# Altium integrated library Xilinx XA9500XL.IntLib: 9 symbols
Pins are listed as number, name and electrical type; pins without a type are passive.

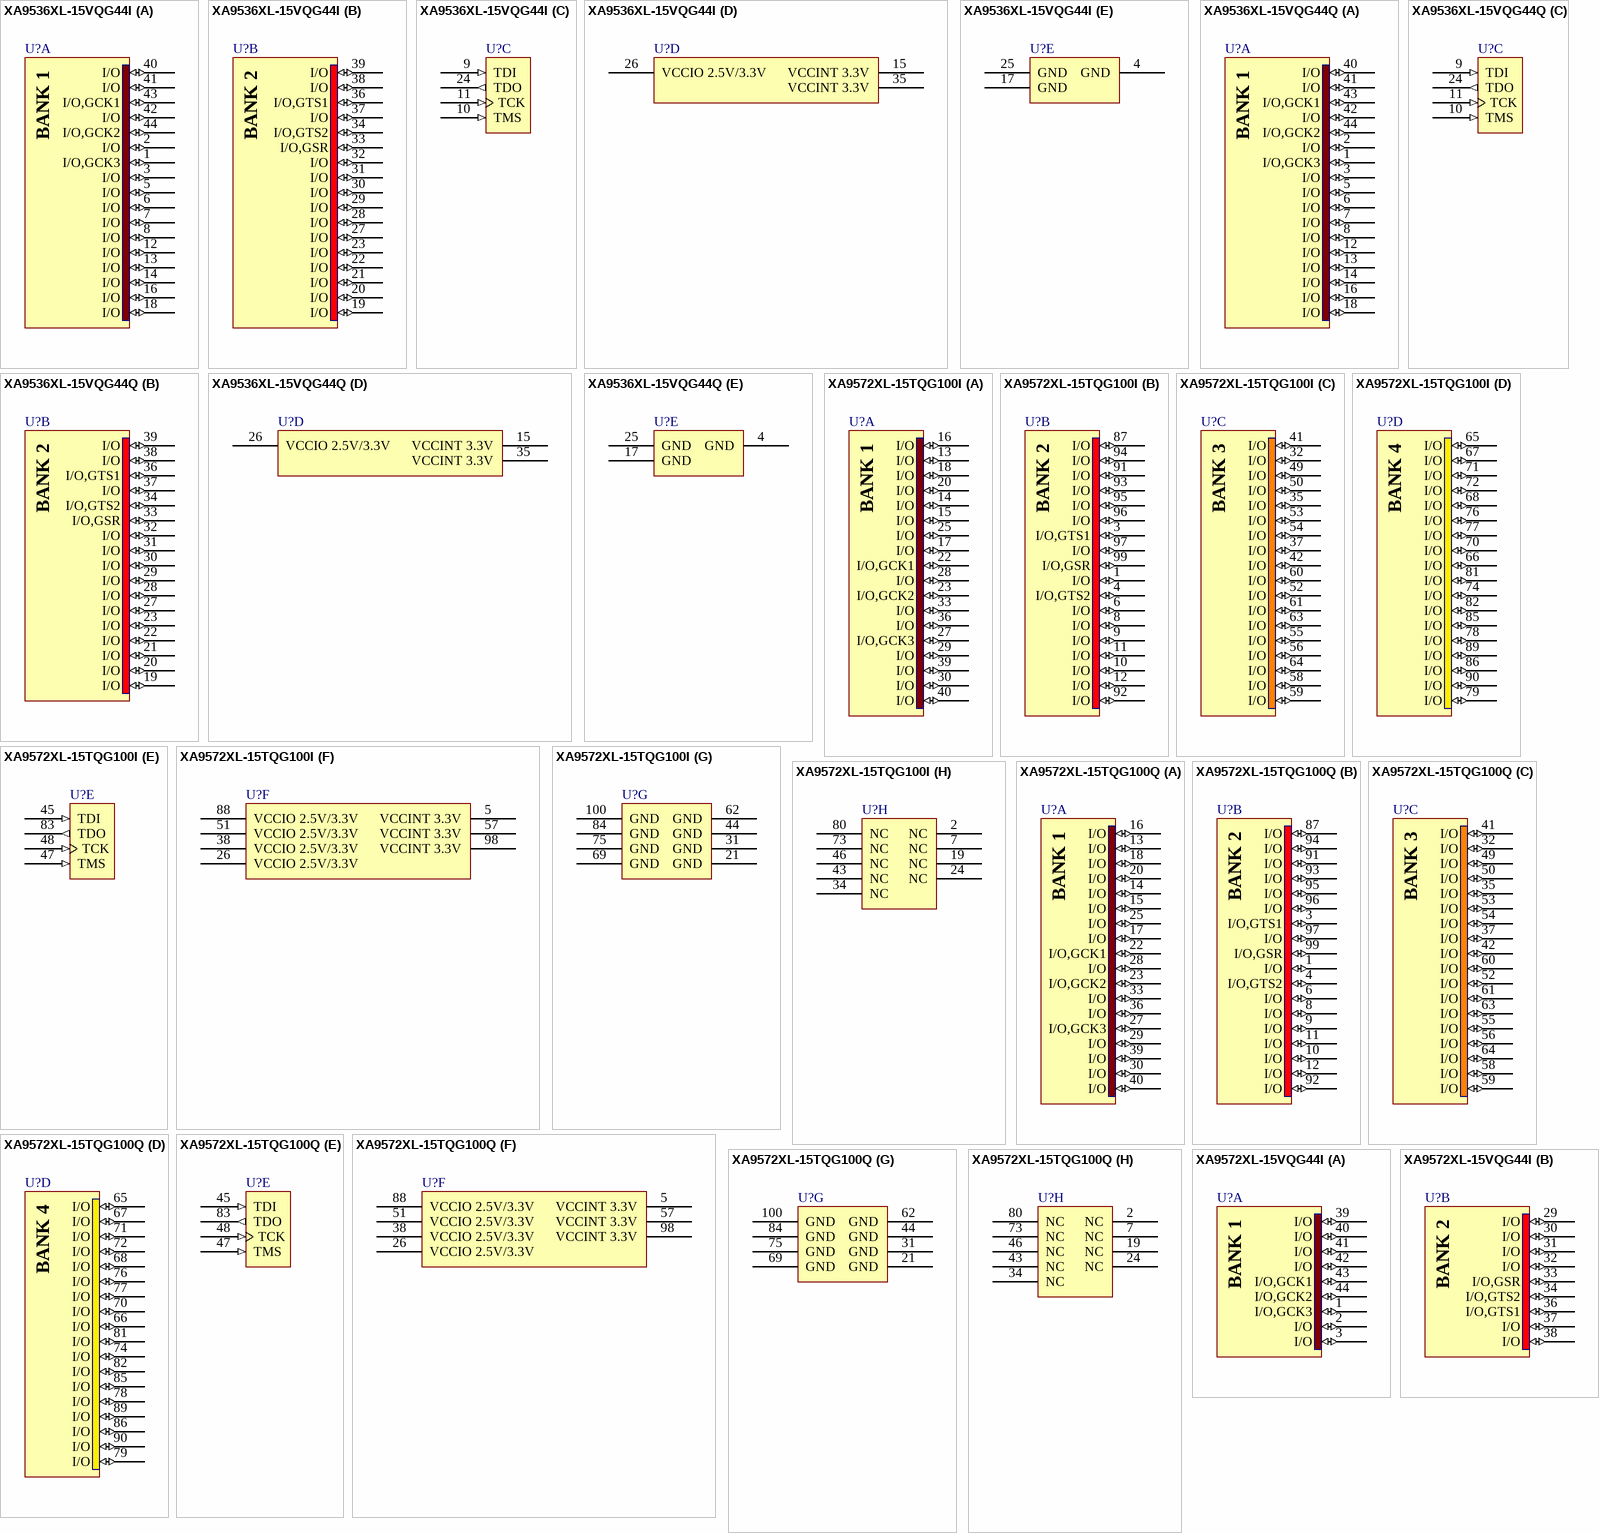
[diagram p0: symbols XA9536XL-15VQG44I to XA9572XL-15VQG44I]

## XA9536XL-15VQG44I
designator U?
XA9500XL Automotive, 36 Macrocell CPLD, 36 User I/Os, 44-Pin VQFP, Speed 15, Industrial Grade, Pb-Free
footprint VQG44_N (Thin QFP, 44-Leads, Body 10x10mm, Pitch 0.8mm, IPC Medium Density)
footprint VQG44_L (Thin QFP, 44-Leads, Body 10x10mm, Pitch 0.8mm, IPC High Density)
footprint VQG44_M (Thin QFP, 44-Leads, Body 10x10mm, Pitch 0.8mm, IPC Low Density)
signal-integrity model XA9536XL_VQ44 (XA9500XL)
part A pins: 1 I/O,GCK3 (io), 2 I/O (io), 3 I/O (io), 5 I/O (io), 6 I/O (io), 7 I/O (io), 8 I/O (io), 12 I/O (io), 13 I/O (io), 14 I/O (io), 16 I/O (io), 18 I/O (io), 40 I/O (io), 41 I/O (io), 42 I/O (io), 43 I/O,GCK1 (io), 44 I/O,GCK2 (io)
part B pins: 19 I/O (io), 20 I/O (io), 21 I/O (io), 22 I/O (io), 23 I/O (io), 27 I/O (io), 28 I/O (io), 29 I/O (io), 30 I/O (io), 31 I/O (io), 32 I/O (io), 33 I/O,GSR (io), 34 I/O,GTS2 (io), 36 I/O,GTS1 (io), 37 I/O (io), 38 I/O (io), 39 I/O (io)
part C pins: 9 TDI (in), 10 TMS (in), 11 TCK (in), 24 TDO (out)
part D pins: 15 VCCINT 3.3V (power), 26 VCCIO 2.5V/3.3V (power), 35 VCCINT 3.3V (power)
part E pins: 4 GND (power), 17 GND (power), 25 GND (power)

## XA9536XL-15VQG44Q
designator U?
XA9500XL Automotive, 36 Macrocell CPLD, 36 User I/Os, 44-Pin VQFP, Speed 15, Q Grade, Pb-Free
footprint VQG44_N (Thin QFP, 44-Leads, Body 10x10mm, Pitch 0.8mm, IPC Medium Density)
footprint VQG44_L (Thin QFP, 44-Leads, Body 10x10mm, Pitch 0.8mm, IPC High Density)
footprint VQG44_M (Thin QFP, 44-Leads, Body 10x10mm, Pitch 0.8mm, IPC Low Density)
signal-integrity model XA9536XL_VQ44 (XA9500XL)
part A pins: 1 I/O,GCK3 (io), 2 I/O (io), 3 I/O (io), 5 I/O (io), 6 I/O (io), 7 I/O (io), 8 I/O (io), 12 I/O (io), 13 I/O (io), 14 I/O (io), 16 I/O (io), 18 I/O (io), 40 I/O (io), 41 I/O (io), 42 I/O (io), 43 I/O,GCK1 (io), 44 I/O,GCK2 (io)
part B pins: 19 I/O (io), 20 I/O (io), 21 I/O (io), 22 I/O (io), 23 I/O (io), 27 I/O (io), 28 I/O (io), 29 I/O (io), 30 I/O (io), 31 I/O (io), 32 I/O (io), 33 I/O,GSR (io), 34 I/O,GTS2 (io), 36 I/O,GTS1 (io), 37 I/O (io), 38 I/O (io), 39 I/O (io)
part C pins: 9 TDI (in), 10 TMS (in), 11 TCK (in), 24 TDO (out)
part D pins: 15 VCCINT 3.3V (power), 26 VCCIO 2.5V/3.3V (power), 35 VCCINT 3.3V (power)
part E pins: 4 GND (power), 17 GND (power), 25 GND (power)

## XA9572XL-15TQG100I
designator U?
XA9500XL Automotive, 72 Macrocell CPLD, 72 User I/Os, 100-Pin TQFP, Speed 15, Industrial Grade, Pb-Free
footprint TQG100_N (Thin QFP, 100-Leads, Body 14x14mm, Pitch 0.5mm, IPC Medium Density)
footprint TQG100_L (Thin QFP, 100-Leads, Body 14x14mm, Pitch 0.5mm, IPC High Density)
footprint TQG100_M (Thin QFP, 100-Leads, Body 14x14mm, Pitch 0.5mm, IPC Low Density)
signal-integrity model XA9572XL_TQ100 (XA9500XL)
part A pins: 13 I/O (io), 14 I/O (io), 15 I/O (io), 16 I/O (io), 17 I/O (io), 18 I/O (io), 20 I/O (io), 22 I/O,GCK1 (io), 23 I/O,GCK2 (io), 25 I/O (io), 27 I/O,GCK3 (io), 28 I/O (io), 29 I/O (io), 30 I/O (io), 33 I/O (io), 36 I/O (io), 39 I/O (io), 40 I/O (io)
part B pins: 1 I/O (io), 3 I/O,GTS1 (io), 4 I/O,GTS2 (io), 6 I/O (io), 8 I/O (io), 9 I/O (io), 10 I/O (io), 11 I/O (io), 12 I/O (io), 87 I/O (io), 91 I/O (io), 92 I/O (io), 93 I/O (io), 94 I/O (io), 95 I/O (io), 96 I/O (io), 97 I/O (io), 99 I/O,GSR (io)
part C pins: 32 I/O (io), 35 I/O (io), 37 I/O (io), 41 I/O (io), 42 I/O (io), 49 I/O (io), 50 I/O (io), 52 I/O (io), 53 I/O (io), 54 I/O (io), 55 I/O (io), 56 I/O (io), 58 I/O (io), 59 I/O (io), 60 I/O (io), 61 I/O (io), 63 I/O (io), 64 I/O (io)
part D pins: 65 I/O (io), 66 I/O (io), 67 I/O (io), 68 I/O (io), 70 I/O (io), 71 I/O (io), 72 I/O (io), 74 I/O (io), 76 I/O (io), 77 I/O (io), 78 I/O (io), 79 I/O (io), 81 I/O (io), 82 I/O (io), 85 I/O (io), 86 I/O (io), 89 I/O (io), 90 I/O (io)
part E pins: 45 TDI (in), 47 TMS (in), 48 TCK (in), 83 TDO (out)
part F pins: 5 VCCINT 3.3V (power), 26 VCCIO 2.5V/3.3V (power), 38 VCCIO 2.5V/3.3V (power), 51 VCCIO 2.5V/3.3V (power), 57 VCCINT 3.3V (power), 88 VCCIO 2.5V/3.3V (power), 98 VCCINT 3.3V (power)
part G pins: 21 GND (power), 31 GND (power), 44 GND (power), 62 GND (power), 69 GND (power), 75 GND (power), 84 GND (power), 100 GND (power)
part H pins: 2 NC, 7 NC, 19 NC, 24 NC, 34 NC, 43 NC, 46 NC, 73 NC, 80 NC

## XA9572XL-15TQG100Q
designator U?
XA9500XL Automotive, 72 Macrocell CPLD, 72 User I/Os, 100-Pin TQFP, Speed 15, Q Grade, Pb-Free
footprint TQG100_N (Thin QFP, 100-Leads, Body 14x14mm, Pitch 0.5mm, IPC Medium Density)
footprint TQG100_L (Thin QFP, 100-Leads, Body 14x14mm, Pitch 0.5mm, IPC High Density)
footprint TQG100_M (Thin QFP, 100-Leads, Body 14x14mm, Pitch 0.5mm, IPC Low Density)
signal-integrity model XA9572XL_TQ100 (XA9500XL)
part A pins: 13 I/O (io), 14 I/O (io), 15 I/O (io), 16 I/O (io), 17 I/O (io), 18 I/O (io), 20 I/O (io), 22 I/O,GCK1 (io), 23 I/O,GCK2 (io), 25 I/O (io), 27 I/O,GCK3 (io), 28 I/O (io), 29 I/O (io), 30 I/O (io), 33 I/O (io), 36 I/O (io), 39 I/O (io), 40 I/O (io)
part B pins: 1 I/O (io), 3 I/O,GTS1 (io), 4 I/O,GTS2 (io), 6 I/O (io), 8 I/O (io), 9 I/O (io), 10 I/O (io), 11 I/O (io), 12 I/O (io), 87 I/O (io), 91 I/O (io), 92 I/O (io), 93 I/O (io), 94 I/O (io), 95 I/O (io), 96 I/O (io), 97 I/O (io), 99 I/O,GSR (io)
part C pins: 32 I/O (io), 35 I/O (io), 37 I/O (io), 41 I/O (io), 42 I/O (io), 49 I/O (io), 50 I/O (io), 52 I/O (io), 53 I/O (io), 54 I/O (io), 55 I/O (io), 56 I/O (io), 58 I/O (io), 59 I/O (io), 60 I/O (io), 61 I/O (io), 63 I/O (io), 64 I/O (io)
part D pins: 65 I/O (io), 66 I/O (io), 67 I/O (io), 68 I/O (io), 70 I/O (io), 71 I/O (io), 72 I/O (io), 74 I/O (io), 76 I/O (io), 77 I/O (io), 78 I/O (io), 79 I/O (io), 81 I/O (io), 82 I/O (io), 85 I/O (io), 86 I/O (io), 89 I/O (io), 90 I/O (io)
part E pins: 45 TDI (in), 47 TMS (in), 48 TCK (in), 83 TDO (out)
part F pins: 5 VCCINT 3.3V (power), 26 VCCIO 2.5V/3.3V (power), 38 VCCIO 2.5V/3.3V (power), 51 VCCIO 2.5V/3.3V (power), 57 VCCINT 3.3V (power), 88 VCCIO 2.5V/3.3V (power), 98 VCCINT 3.3V (power)
part G pins: 21 GND (power), 31 GND (power), 44 GND (power), 62 GND (power), 69 GND (power), 75 GND (power), 84 GND (power), 100 GND (power)
part H pins: 2 NC, 7 NC, 19 NC, 24 NC, 34 NC, 43 NC, 46 NC, 73 NC, 80 NC

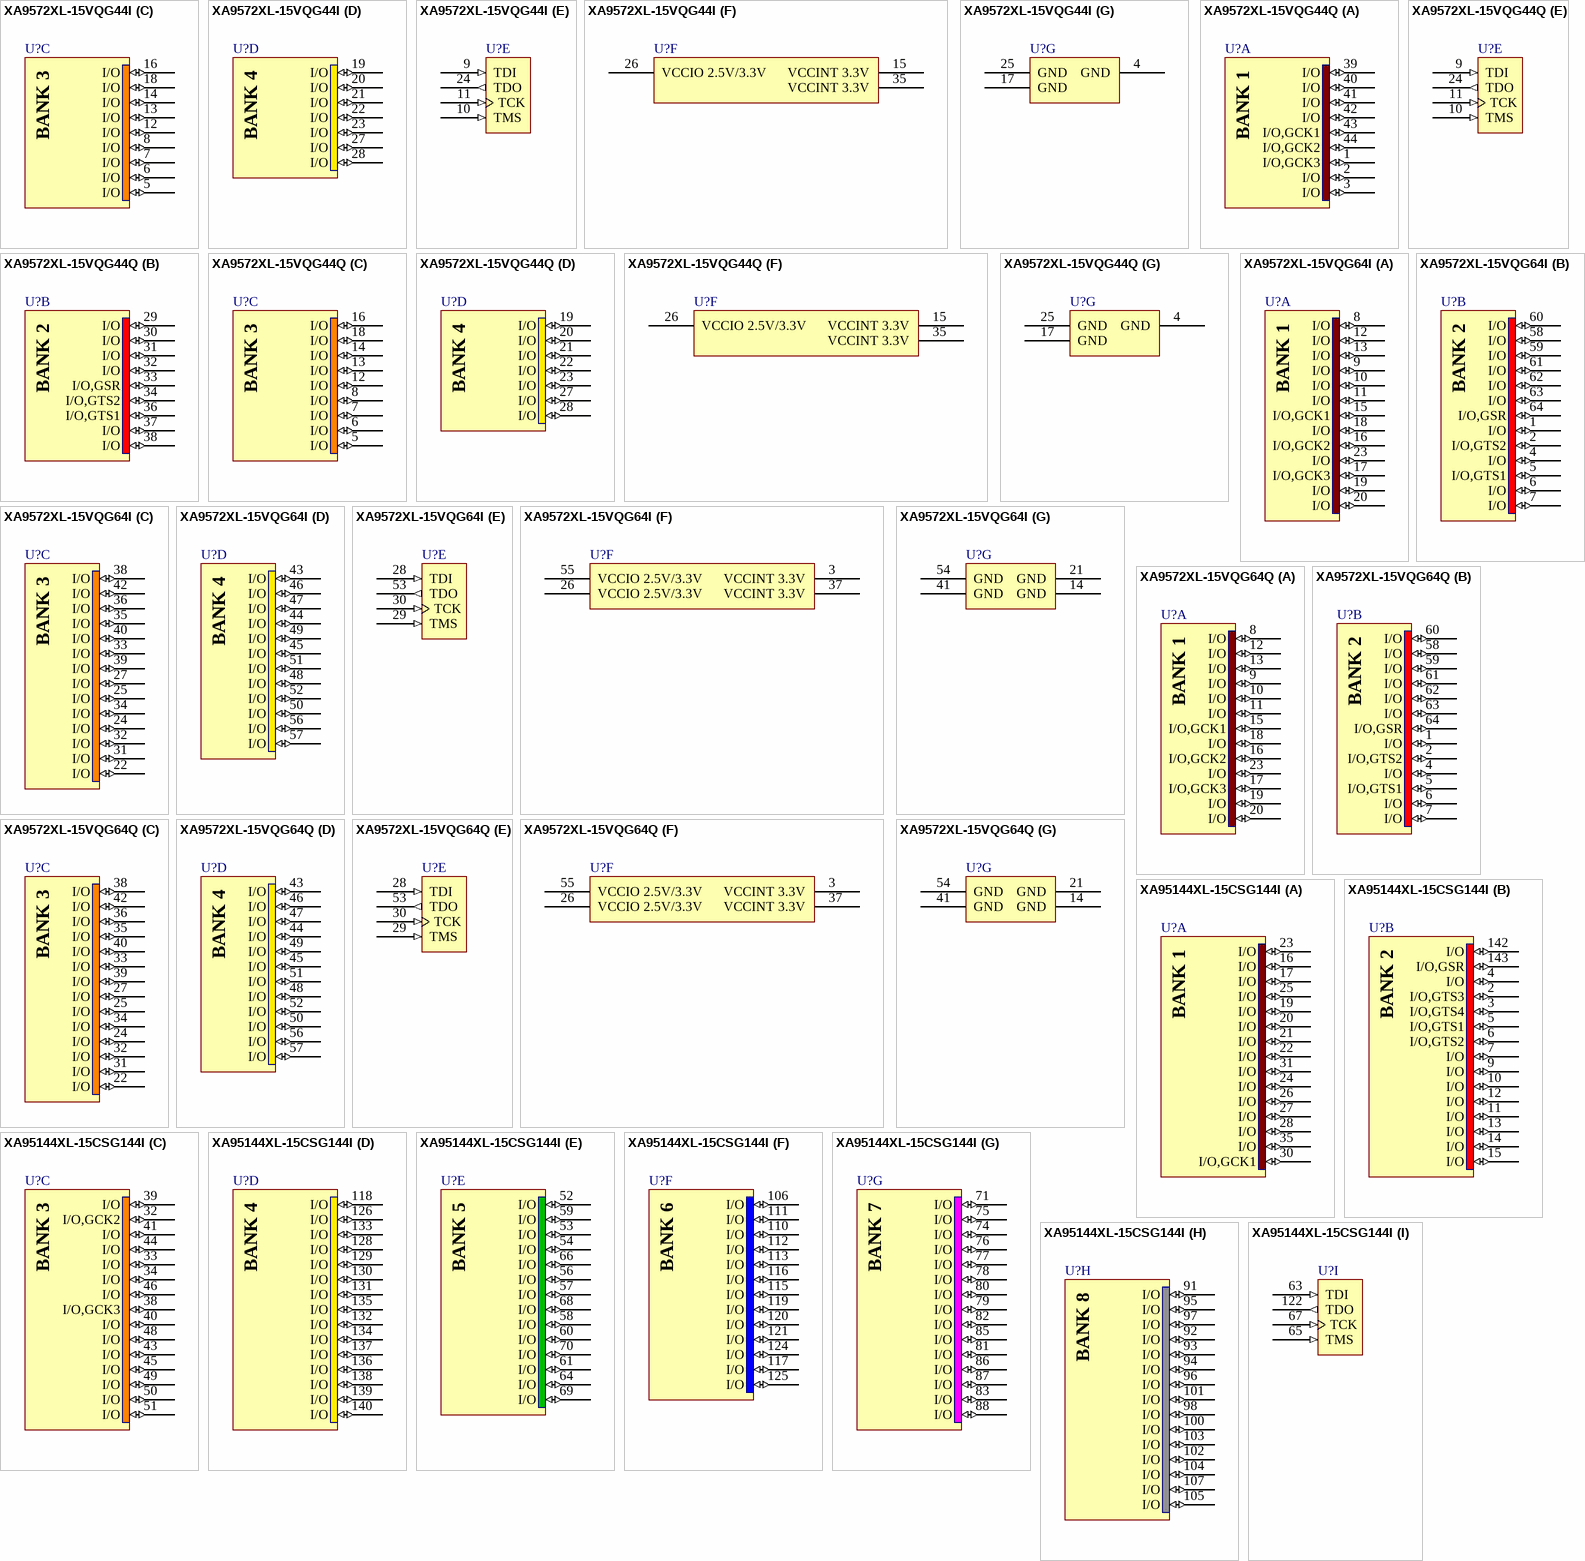
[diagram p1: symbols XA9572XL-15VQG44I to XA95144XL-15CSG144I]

## XA9572XL-15VQG44I
designator U?
XA9500XL Automotive, 72 Macrocell CPLD, 34 User I/Os, 44-Pin VQFP, Speed 15, Industrial Grade, Pb-Free
footprint VQG44_N (Thin QFP, 44-Leads, Body 10x10mm, Pitch 0.8mm, IPC Medium Density)
footprint VQG44_L (Thin QFP, 44-Leads, Body 10x10mm, Pitch 0.8mm, IPC High Density)
footprint VQG44_M (Thin QFP, 44-Leads, Body 10x10mm, Pitch 0.8mm, IPC Low Density)
signal-integrity model XA9572XL_VQ44 (XA9500XL)
part A pins: 1 I/O,GCK3 (io), 2 I/O (io), 3 I/O (io), 39 I/O (io), 40 I/O (io), 41 I/O (io), 42 I/O (io), 43 I/O,GCK1 (io), 44 I/O,GCK2 (io)
part B pins: 29 I/O (io), 30 I/O (io), 31 I/O (io), 32 I/O (io), 33 I/O,GSR (io), 34 I/O,GTS2 (io), 36 I/O,GTS1 (io), 37 I/O (io), 38 I/O (io)
part C pins: 5 I/O (io), 6 I/O (io), 7 I/O (io), 8 I/O (io), 12 I/O (io), 13 I/O (io), 14 I/O (io), 16 I/O (io), 18 I/O (io)
part D pins: 19 I/O (io), 20 I/O (io), 21 I/O (io), 22 I/O (io), 23 I/O (io), 27 I/O (io), 28 I/O (io)
part E pins: 9 TDI (in), 10 TMS (in), 11 TCK (in), 24 TDO (out)
part F pins: 15 VCCINT 3.3V (power), 26 VCCIO 2.5V/3.3V (power), 35 VCCINT 3.3V (power)
part G pins: 4 GND (power), 17 GND (power), 25 GND (power)

## XA9572XL-15VQG44Q
designator U?
XA9500XL Automotive, 72 Macrocell CPLD, 34 User I/Os, 44-Pin VQFP, Speed 15, Q Grade, Pb-Free
footprint VQG44_N (Thin QFP, 44-Leads, Body 10x10mm, Pitch 0.8mm, IPC Medium Density)
footprint VQG44_L (Thin QFP, 44-Leads, Body 10x10mm, Pitch 0.8mm, IPC High Density)
footprint VQG44_M (Thin QFP, 44-Leads, Body 10x10mm, Pitch 0.8mm, IPC Low Density)
signal-integrity model XA9572XL_VQ44 (XA9500XL)
part A pins: 1 I/O,GCK3 (io), 2 I/O (io), 3 I/O (io), 39 I/O (io), 40 I/O (io), 41 I/O (io), 42 I/O (io), 43 I/O,GCK1 (io), 44 I/O,GCK2 (io)
part B pins: 29 I/O (io), 30 I/O (io), 31 I/O (io), 32 I/O (io), 33 I/O,GSR (io), 34 I/O,GTS2 (io), 36 I/O,GTS1 (io), 37 I/O (io), 38 I/O (io)
part C pins: 5 I/O (io), 6 I/O (io), 7 I/O (io), 8 I/O (io), 12 I/O (io), 13 I/O (io), 14 I/O (io), 16 I/O (io), 18 I/O (io)
part D pins: 19 I/O (io), 20 I/O (io), 21 I/O (io), 22 I/O (io), 23 I/O (io), 27 I/O (io), 28 I/O (io)
part E pins: 9 TDI (in), 10 TMS (in), 11 TCK (in), 24 TDO (out)
part F pins: 15 VCCINT 3.3V (power), 26 VCCIO 2.5V/3.3V (power), 35 VCCINT 3.3V (power)
part G pins: 4 GND (power), 17 GND (power), 25 GND (power)

## XA9572XL-15VQG64I
designator U?
XA9500XL Automotive, 72 Macrocell CPLD, 52 User I/Os, 64-Pin VQFP, Speed 15, Industrial Grade, Pb-Free
footprint VQG64_N (Thin QFP, 64-Leads, Body 10x10mm, Pitch 0.5mm, IPC Medium Density)
footprint VQG64_L (Thin QFP, 64-Leads, Body 10x10mm, Pitch 0.5mm, IPC High Density)
footprint VQG64_M (Thin QFP, 64-Leads, Body 10x10mm, Pitch 0.5mm, IPC Low Density)
signal-integrity model XA9572XL_VQ64 (XA9500XL)
part A pins: 8 I/O (io), 9 I/O (io), 10 I/O (io), 11 I/O (io), 12 I/O (io), 13 I/O (io), 15 I/O,GCK1 (io), 16 I/O,GCK2 (io), 17 I/O,GCK3 (io), 18 I/O (io), 19 I/O (io), 20 I/O (io), 23 I/O (io)
part B pins: 1 I/O (io), 2 I/O,GTS2 (io), 4 I/O (io), 5 I/O,GTS1 (io), 6 I/O (io), 7 I/O (io), 58 I/O (io), 59 I/O (io), 60 I/O (io), 61 I/O (io), 62 I/O (io), 63 I/O (io), 64 I/O,GSR (io)
part C pins: 22 I/O (io), 24 I/O (io), 25 I/O (io), 27 I/O (io), 31 I/O (io), 32 I/O (io), 33 I/O (io), 34 I/O (io), 35 I/O (io), 36 I/O (io), 38 I/O (io), 39 I/O (io), 40 I/O (io), 42 I/O (io)
part D pins: 43 I/O (io), 44 I/O (io), 45 I/O (io), 46 I/O (io), 47 I/O (io), 48 I/O (io), 49 I/O (io), 50 I/O (io), 51 I/O (io), 52 I/O (io), 56 I/O (io), 57 I/O (io)
part E pins: 28 TDI (in), 29 TMS (in), 30 TCK (in), 53 TDO (out)
part F pins: 3 VCCINT 3.3V (power), 26 VCCIO 2.5V/3.3V (power), 37 VCCINT 3.3V (power), 55 VCCIO 2.5V/3.3V (power)
part G pins: 14 GND (power), 21 GND (power), 41 GND (power), 54 GND (power)

## XA9572XL-15VQG64Q
designator U?
XA9500XL Automotive, 72 Macrocell CPLD, 52 User I/Os, 64-Pin VQFP, Speed 15, Q Grade, Pb-Free
footprint VQG64_N (Thin QFP, 64-Leads, Body 10x10mm, Pitch 0.5mm, IPC Medium Density)
footprint VQG64_L (Thin QFP, 64-Leads, Body 10x10mm, Pitch 0.5mm, IPC High Density)
footprint VQG64_M (Thin QFP, 64-Leads, Body 10x10mm, Pitch 0.5mm, IPC Low Density)
signal-integrity model XA9572XL_VQ64 (XA9500XL)
part A pins: 8 I/O (io), 9 I/O (io), 10 I/O (io), 11 I/O (io), 12 I/O (io), 13 I/O (io), 15 I/O,GCK1 (io), 16 I/O,GCK2 (io), 17 I/O,GCK3 (io), 18 I/O (io), 19 I/O (io), 20 I/O (io), 23 I/O (io)
part B pins: 1 I/O (io), 2 I/O,GTS2 (io), 4 I/O (io), 5 I/O,GTS1 (io), 6 I/O (io), 7 I/O (io), 58 I/O (io), 59 I/O (io), 60 I/O (io), 61 I/O (io), 62 I/O (io), 63 I/O (io), 64 I/O,GSR (io)
part C pins: 22 I/O (io), 24 I/O (io), 25 I/O (io), 27 I/O (io), 31 I/O (io), 32 I/O (io), 33 I/O (io), 34 I/O (io), 35 I/O (io), 36 I/O (io), 38 I/O (io), 39 I/O (io), 40 I/O (io), 42 I/O (io)
part D pins: 43 I/O (io), 44 I/O (io), 45 I/O (io), 46 I/O (io), 47 I/O (io), 48 I/O (io), 49 I/O (io), 50 I/O (io), 51 I/O (io), 52 I/O (io), 56 I/O (io), 57 I/O (io)
part E pins: 28 TDI (in), 29 TMS (in), 30 TCK (in), 53 TDO (out)
part F pins: 3 VCCINT 3.3V (power), 26 VCCIO 2.5V/3.3V (power), 37 VCCINT 3.3V (power), 55 VCCIO 2.5V/3.3V (power)
part G pins: 14 GND (power), 21 GND (power), 41 GND (power), 54 GND (power)

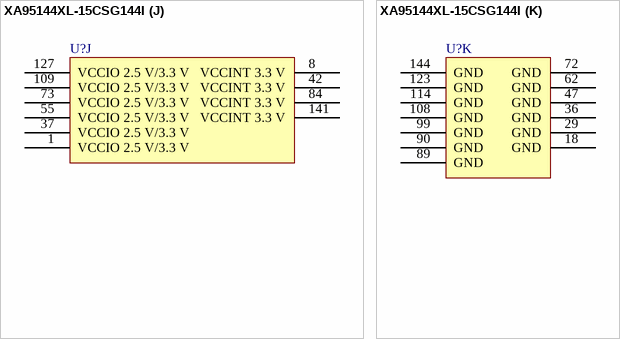
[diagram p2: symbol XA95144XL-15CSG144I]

## XA95144XL-15CSG144I
designator U?
XA9500XL Automotive, 144 Macrocell CPLD, 117 User I/Os, 100-Pin TQFP, Speed 15, Industrial Grade, Pb-Free
footprint TQG144_N (Thin QFP, 144-Leads, Body 20x20mm, Pitch 0.5mm, IPC Medium Density)
footprint TQG144_L (Thin QFP, 144-Leads, Body 20x20mm, Pitch 0.5mm, IPC High Density)
footprint TQG144_M (Thin QFP, 144-Leads, Body 20x20mm, Pitch 0.5mm, IPC Low Density)
signal-integrity model XA95144XL_CS144 (XA9500XL)
part A pins: 16 I/O (io), 17 I/O (io), 19 I/O (io), 20 I/O (io), 21 I/O (io), 22 I/O (io), 23 I/O (io), 24 I/O (io), 25 I/O (io), 26 I/O (io), 27 I/O (io), 28 I/O (io), 30 I/O,GCK1 (io), 31 I/O (io), 35 I/O (io)
part B pins: 2 I/O,GTS3 (io), 3 I/O,GTS4 (io), 4 I/O (io), 5 I/O,GTS1 (io), 6 I/O,GTS2 (io), 7 I/O (io), 9 I/O (io), 10 I/O (io), 11 I/O (io), 12 I/O (io), 13 I/O (io), 14 I/O (io), 15 I/O (io), 142 I/O (io), 143 I/O,GSR (io)
part C pins: 32 I/O,GCK2 (io), 33 I/O (io), 34 I/O (io), 38 I/O,GCK3 (io), 39 I/O (io), 40 I/O (io), 41 I/O (io), 43 I/O (io), 44 I/O (io), 45 I/O (io), 46 I/O (io), 48 I/O (io), 49 I/O (io), 50 I/O (io), 51 I/O (io)
part D pins: 118 I/O (io), 126 I/O (io), 128 I/O (io), 129 I/O (io), 130 I/O (io), 131 I/O (io), 132 I/O (io), 133 I/O (io), 134 I/O (io), 135 I/O (io), 136 I/O (io), 137 I/O (io), 138 I/O (io), 139 I/O (io), 140 I/O (io)
part E pins: 52 I/O (io), 53 I/O (io), 54 I/O (io), 56 I/O (io), 57 I/O (io), 58 I/O (io), 59 I/O (io), 60 I/O (io), 61 I/O (io), 64 I/O (io), 66 I/O (io), 68 I/O (io), 69 I/O (io), 70 I/O (io)
part F pins: 106 I/O (io), 110 I/O (io), 111 I/O (io), 112 I/O (io), 113 I/O (io), 115 I/O (io), 116 I/O (io), 117 I/O (io), 119 I/O (io), 120 I/O (io), 121 I/O (io), 124 I/O (io), 125 I/O (io)
part G pins: 71 I/O (io), 74 I/O (io), 75 I/O (io), 76 I/O (io), 77 I/O (io), 78 I/O (io), 79 I/O (io), 80 I/O (io), 81 I/O (io), 82 I/O (io), 83 I/O (io), 85 I/O (io), 86 I/O (io), 87 I/O (io), 88 I/O (io)
part H pins: 91 I/O (io), 92 I/O (io), 93 I/O (io), 94 I/O (io), 95 I/O (io), 96 I/O (io), 97 I/O (io), 98 I/O (io), 100 I/O (io), 101 I/O (io), 102 I/O (io), 103 I/O (io), 104 I/O (io), 105 I/O (io), 107 I/O (io)
part I pins: 63 TDI (in), 65 TMS (in), 67 TCK (in), 122 TDO (out)
part J pins: 1 VCCIO 2.5 V/3.3 V (power), 8 VCCINT 3.3 V (power), 37 VCCIO 2.5 V/3.3 V (power), 42 VCCINT 3.3 V (power), 55 VCCIO 2.5 V/3.3 V (power), 73 VCCIO 2.5 V/3.3 V (power), 84 VCCINT 3.3 V (power), 109 VCCIO 2.5 V/3.3 V (power), 127 VCCIO 2.5 V/3.3 V (power), 141 VCCINT 3.3 V (power)
part K pins: 18 GND (power), 29 GND (power), 36 GND (power), 47 GND (power), 62 GND (power), 72 GND (power), 89 GND (power), 90 GND (power), 99 GND (power), 108 GND (power), 114 GND (power), 123 GND (power), 144 GND (power)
